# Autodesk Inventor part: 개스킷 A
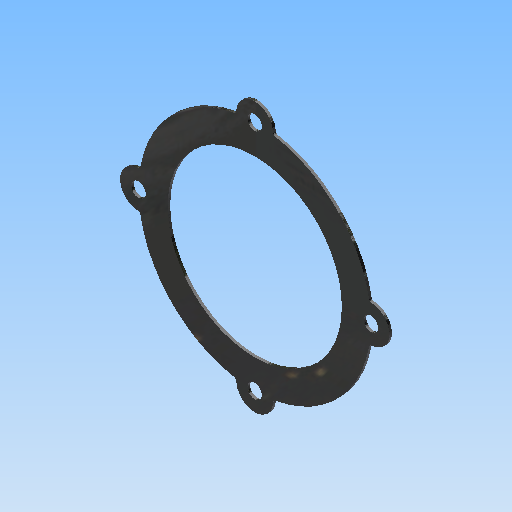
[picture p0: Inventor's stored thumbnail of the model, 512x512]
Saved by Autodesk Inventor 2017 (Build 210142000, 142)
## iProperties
Created: 2020-03
Part Number: 개스킷 A
Material: 고무
Document SubType Name: Modeling
Designer: mduedu
Density: 0.93 g/cm^3
Mass: 2.68337 g
Surface Area: 63.575 cm^2
Volume: 2.88534 cm^3
Appearance: 고무 - 검은색 - 버전 1.1
Author: mduedu
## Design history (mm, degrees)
sketch "스케치1" dims "d1" = 88
  geometry: C1 r 33 at (0, 0); C2 r 7 at (0, 44); C3 r 7 at (-38.105, -22); C4 r 7 at (38.105, -22); 2 further points
  constraints: 4 centre point, 2 coincident, 2 vertical alignment, 9 other
  dimensions: "d0" = 66 diameter of C1; "d2" = 14 diameter of C2; "d5" = 360 deg dimension on point (0, 0) C2.centre (derived)
extrude "돌출1" new body sketch "스케치1" distance "d7" = 1; taper "d8" = 0 deg
extrude "돌출2" join sketch "스케치1" stored distance "d17" = 10; taper "d18" = 0 deg
fillet "모깎기1" dims "d9" = 1
sketch "스케치2"
  geometry: C1 r 33 at (0, 0) reference; A1 r 44 centre (0, 0) between (-7.817, 43.3) and (7.817, 43.3) reference; A2 r 7 centre (0, 44) between (6.996, 44.249) and (-6.996, 44.249) reference; A3 r 1 centre (7.995, 44.284) between (6.996, 44.249) and (7.817, 43.3) reference; A4 r 1 centre (-7.995, 44.284) between (-7.817, 43.3) and (-6.996, 44.249) reference; 4 further points
hole "구멍1" sketch "스케치2" diameter "d10" = 5.5; stored, may be unused: countersink angle "d14" = 90 deg, drill point angle "d16" = 118 deg; dims "d11" = 6, "d12" = 10, "d13" = 5.7, "d15" = 8
node "솔리드1"
pattern_circular "원형 패턴1" dims angle "d20" = 360 deg
node "투영된 루프1"
